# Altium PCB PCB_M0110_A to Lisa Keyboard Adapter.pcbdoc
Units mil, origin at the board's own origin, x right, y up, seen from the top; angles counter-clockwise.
Board outline 2510 x 3305 mil, 2 copper layers (Top Layer, Bottom Layer); 7 components, 17 nets, 64 pads, 0 vias.
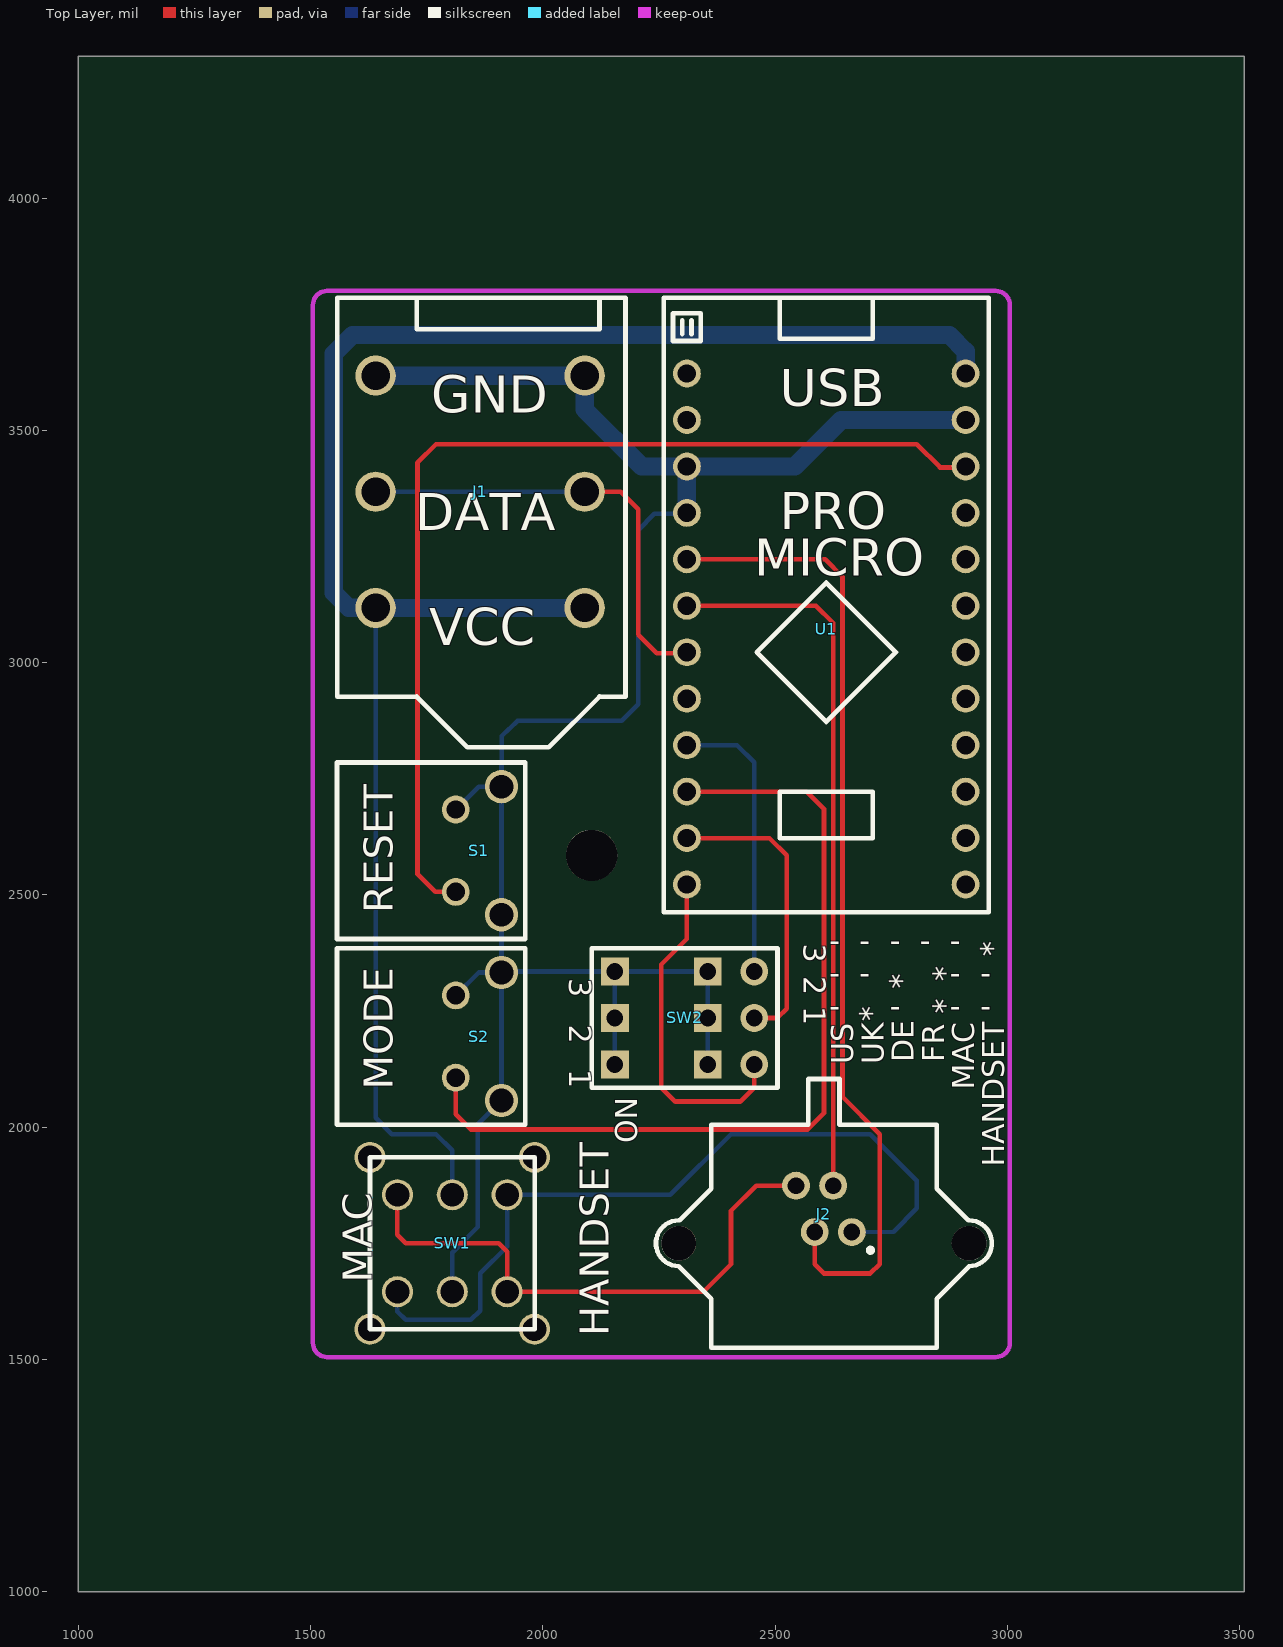
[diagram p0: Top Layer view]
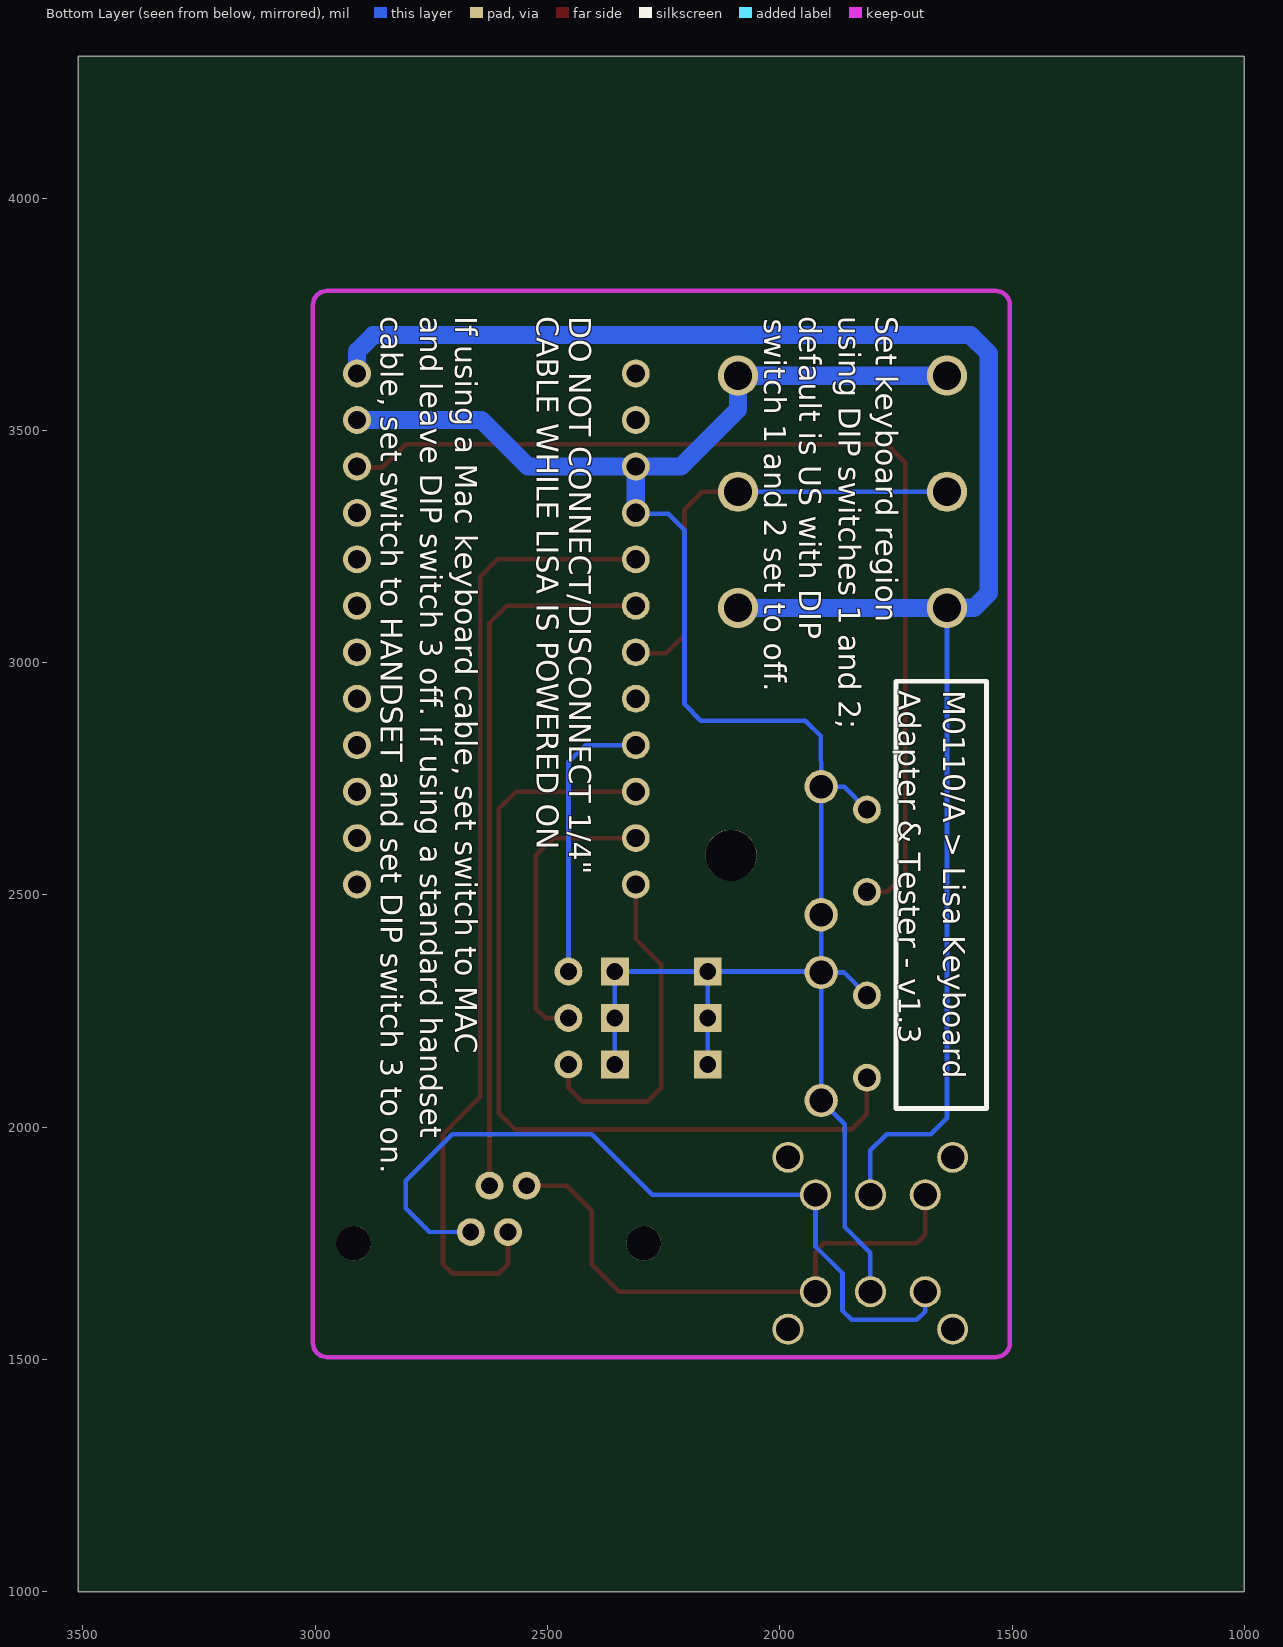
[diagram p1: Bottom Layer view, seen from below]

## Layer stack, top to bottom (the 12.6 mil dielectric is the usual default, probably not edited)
Top Layer: signal copper (thickness not stored)
Dielectric: dielectric 12.6, FR-4, Dk 4.8
Bottom Layer: signal copper (thickness not stored)

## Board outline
3510,1000 1000,1000 1000,4305 3510,4305

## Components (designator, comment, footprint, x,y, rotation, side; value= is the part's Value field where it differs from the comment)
J1 "Lisa Keyboard Connector" TRS_STEREO_0.25_INCH 1640,3117.7 r0 top
J2 "Mac Plus Keyboard Connector" MAC_KBD_CONNECTOR_ALT 2605,1750 r0 top
S1 "Tact Switch - 6mm - Right Angle" TACT_SWITCH_RIGHT_ANGLE_6MM 1861.69,2595 r270 top
S2 "Tact Switch - 6mm - Right Angle" TACT_SWITCH_RIGHT_ANGLE_6MM 1861.69,2195 r270 top
SW1 "DPDT_SLIDER_SWITCH" DPDT_SLIDER_SWITCH 1805,1750 r0 top
SW2 "DIP_SWITCH_3POS" DIP_SWITCH_3POS 2305,2235 r0 top
U1 "Arduino Pro Micro" ARDUINO_PRO_MICRO 2310,3622.2 r0 top

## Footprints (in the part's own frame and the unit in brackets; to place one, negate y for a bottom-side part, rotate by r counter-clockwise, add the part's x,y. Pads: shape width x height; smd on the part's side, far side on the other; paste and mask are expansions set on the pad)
ARDUINO_PRO_MICRO [mil]
  round 60 hole 39.37: 1(0,0) 2(0,-100) 3(0,-200) 4(0,-300) 5(0,-400) 6(0,-500) 7(0,-600) 8(0,-700) 9(0,-800) 10(0,-900) 11(0,-1000) 12(0,-1100) 13(600,-1100) 14(600,-1000) 15(600,-900) 16(600,-800) 17(600,-700) 18(600,-600) 19(600,-500) 20(600,-400) 21(600,-300) 22(600,-200) 23(600,-100) 24(600,0)
  silkscreen extent -50,-1160 650,163
DIP_SWITCH_3POS [mil]
  rect 60x60 hole 36: 1(-150,100) 2(-150,0) 3(-150,-100)
  round 60 hole 36: 4(150,-100) 5(150,0) 6(150,100)
  silkscreen extent -200,-150 200,150
DPDT_SLIDER_SWITCH [mm]
  round 1.7 hole 1.3: 1(-3,2.65) 2(0,2.65) 3(3,2.65) 4(-3,-2.65) 5(0,-2.65) 6(3,-2.65) ""(-4.5,-4.7) ""(-4.5,4.7) ""(4.5,-4.7) ""(4.5,4.7)
  silkscreen extent -4.5,-4.7 4.5,4.7
MAC_KBD_CONNECTOR_ALT [mil]
  round 60 hole 35.98: 1(60.04,24.02) 2(19.88,124.02) 3(-19.88,24.02) 4(-60.04,124.02)
  round 74.8 hole 74.8 unplated: ""(-312.4,0) ""(312.4,0)
  silkscreen extent -361,-225 361,354
TACT_SWITCH_RIGHT_ANGLE_6MM [mm]
  round 1.524 hole 1: 1(2.25,-1.25) 2(-2.25,-1.25)
  round 1.824 hole 1.3: 3(3.5,1.25) 4(-3.5,1.25)
  silkscreen extent -4.83,-7.75 4.83,2.54
TRS_STEREO_0.25_INCH [mm]
  round 2.2 hole 1.55: 1(0,0) 2(0,6.35) 3(0,12.7) 4(11.43,0) 5(11.43,6.35) 6(11.43,12.7)
  silkscreen extent -2.09,-7.62 13.66,16.95

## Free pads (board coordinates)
  rect 60x60 hole 36: 1(2355,2335) 2(2355,2235) 3(2355,2135)
  round 110.24 hole 110.24 unplated: ""(2105,2585)

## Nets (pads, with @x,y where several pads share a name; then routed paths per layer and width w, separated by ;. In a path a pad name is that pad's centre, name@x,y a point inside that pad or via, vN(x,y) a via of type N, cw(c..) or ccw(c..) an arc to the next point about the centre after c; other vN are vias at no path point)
CABLE: SW2.6 U1.9 | length 610.4
  Bottom Layer w10: U1.9 2417.8,2822.2 2455,2785 SW2.6
DE/FR: SW2.5 U1.11 | length 638.7
  Top Layer w10: U1.11 2487.8,2622.2 2525,2585 2525,2255 2505,2235 SW2.5
GND: J1.3 J1.6 pad.1 pad.2 pad.3 S1.2 S1.3 S1.4 S2.2 S2.3 S2.4 SW1.5 SW2.1 SW2.2 SW2.3 U1.3 U1.4 U1.23 | length 4673.4
  Bottom Layer w10: SW1.5 1805,1730 1860,1785 1860,2006.3 S2.3 S2.4 ; S2.2 1861.69,2332.79 S2.4 ; S1.2 1861.69,2732.79 S1.4 ; SW2.3 SW2.2 SW2.1 ; U1.4@2310,3320 2240,3320 2205,3285 2205,2910 2170,2875 1945.5,2875 1911.8,2841.9 S1.4 ; pad.3 pad.2 pad.1 SW2.1 ; S2.4 1913.11,2335 SW2.1 ; S2.4 S1.3 S1.4
  Bottom Layer w39.37: J1.3 J1.6 2090,3545 2212.8,3422.2 U1.3 ; U1.4 U1.3 ; U1.23 2642.2,3522.2 2542.2,3422.2 U1.3
GND/VCC: J2.1 SW1.3 SW1.4 | length 1708
  Bottom Layer w10: SW1.4 1686.9,1603.1 1705,1585 1845,1585 1865,1605 1865,1685 1923.1,1743.1 SW1.3 ; SW1.3 2274.3,1854.3 2405,1985 2705,1985 2805,1885 2805,1825 2755,1775 J2.1
LISA_DATA: J1.2 J1.5 U1.7 | length 972.2
  Top Layer w10: J1.5 2167.3,3367.7 2205,3330 2205,3060 2245,3020 U1.7@2310,3020
  Bottom Layer w10: J1.2 J1.5
M0110_CLOCK: J2.2 U1.6 | length 1541.4
  Top Layer w10: U1.6 2587.8,3122.2 2624.9,3085.1 J2.2
M0110_DATA: J2.3 U1.5 | length 2089.1
  Top Layer w10: U1.5 2607.8,3222.2 2645,3185 2645,2065 2725,1985 2725,1705 2705,1685 2605,1685 2585.1,1704.9 J2.3
MOD: S2.1 U1.10 | length 1864.8
  Top Layer w10: S2.1 1812.5,2027.5 1845,1995 2570,1995 2605,2030 2605,2685 2567.8,2722.2 U1.10
RESET: S1.1 U1.22 | length 2200.8
  Top Layer w10: S1.1 1768.6,2506.4 1730,2545 1730,3430 1770,3470 2805,3470 2855,3420 U1.22@2910,3420
S$3616: 
S$4501: 
S$4544: 
S$4548: 
S$11069: 
US/UK: SW2.4 U1.12 | length 734.8
  Top Layer w10: U1.12 2310,2405 2255,2350 2255,2085 2285,2055 2425,2055 2455,2085 SW2.4
VCC: J1.1 J1.4 SW1.2 U1.24 | length 3894.6
  Bottom Layer w10: J1.1 1640,2020 1675,1985 1770,1985 1805,1950 SW1.2
  Bottom Layer w39.37: J1.4 J1.1 1582.3,3117.7 1550,3150 1550,3665 1590,3705 2875,3705 2910,3670 U1.24
VCC/GND: J2.4 SW1.1 SW1.6 | length 1207.4
  Top Layer w10: SW1.1 1686.9,1768.1 1705,1750 1905,1750 1923.1,1731.9 SW1.6 ; SW1.6 2345.7,1645.7 2405,1705 2405,1820 2459,1874 J2.4
pads on no net: J2. SW1. U1.1 U1.2 U1.8 U1.13 U1.14 U1.15 U1.16 U1.17 U1.18 U1.19 U1.20 U1.21

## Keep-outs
Keep-Out Layer:
  lines w10: 1505,1535 ccw(c1535,1535) 1535,1505 ; 1505,3770 cw(c1535,3770) 1535,3800 ; 2975,1505 ccw(c2975,1535) 3005,1535 ; 2975,3800 cw(c2975,3770) 3005,3770

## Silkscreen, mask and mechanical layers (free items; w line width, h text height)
Top Overlay:
  text "RESET" at 1676.5,2460 h62.99 r90
  text "*" at 2952.83,2420.25 h47.24 r211
  text "-" at 2640,2413.62 h47.24 r180
  text "-" at 2705,2413.62 h47.24 r180
  text "-" at 2770,2413.62 h47.24 r180
  text "-" at 2835,2413.62 h47.24 r180
  text "-" at 2900,2413.62 h47.24 r180
  text "3" at 2561.38,2395 h47.24 r270
  text "*" at 2757.83,2350.25 h47.24 r211
  text "-" at 2640,2343.62 h47.24 r180
  text "-" at 2705,2343.62 h47.24 r180
  text "-" at 2900,2343.62 h47.24 r180
  text "-" at 2965,2343.62 h47.24 r180
  text "2" at 2561.38,2325 h47.24 r270
  text "3" at 2056.38,2320 h47.24 r270
  text "*" at 2822.83,2309.75 h47.24 r329
  text "*" at 2692.83,2280.25 h47.24 r211
  text "-" at 2640,2273.62 h47.24 r180
  text "-" at 2770,2273.62 h47.24 r180
  text "-" at 2900,2273.62 h47.24 r180
  text "-" at 2965,2273.62 h47.24 r180
  text "1" at 2561.38,2260 h47.24 r270
  text "*" at 2822.83,2239.75 h47.24 r329
  text "2" at 2056.38,2220 h47.24 r270
  text "DE" at 2798.62,2140 h47.24 r90
  text "FR" at 2863.62,2140 h47.24 r90
  text "US" at 2668.62,2135 h47.24 r90
  text "UK" at 2733.62,2135 h47.24 r90
  text "1" at 2056.38,2125 h47.24 r270
  text "MODE" at 1676.5,2080 h62.99 r90
  text "MAC" at 2928.62,2080 h47.24 r90
  text "ON" at 2203.62,1965 h47.24 r90
  text "HANDSET" at 2993.62,1915 h47.24 r90
  text "MAC" at 1631.5,1665 h62.99 r90
  text "HANDSET" at 2141.5,1550 h62.99 r90
Bottom Overlay:
  lines w10 net S$11069: 1555,2040 1750,2040 1750,2960 1555,2960 1555,2040
  text "Set keyboard region" at 1793.62,3745 h47.24 r90
  text "using DIP switches 1 and 2;" at 1873.62,3745 h47.24 r90
  text "default is US with DIP" at 1958.62,3745 h47.24 r90
  text "DO NOT CONNECT/DISCONNECT 1/4\"" at 2453.62,3745 h47.24 r90
  text "CABLE WHILE LISA IS POWERED ON" at 2523.62,3745 h47.24 r90
  text "If using a Mac keyboard cable, set switch to MAC" at 2698.62,3745 h47.24 r90
  text "and leave DIP switch 3 off. If using a standard handset" at 2773.62,3745 h47.24 r90
  text "cable, set switch to HANDSET and set DIP switch 3 to on." at 2858.62,3745 h47.24 r90
  text "switch 1 and 2 set to off." at 2033.62,3740 h47.24 r90
  text "M0110/A > Lisa Keyboard" at 1648.62,2940 h47.24 r90
  text "Adapter & Tester - v1.3" at 1743.62,2940 h47.24 r90
Document:
  lines w0.1: 2254.99,2652.49 2255.01,2652.51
